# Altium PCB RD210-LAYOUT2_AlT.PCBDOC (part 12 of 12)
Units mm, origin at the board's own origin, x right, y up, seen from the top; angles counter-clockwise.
Board outline 250 x 123 mm, 4 copper layers (TOP, Mid-Layer 1, Mid-Layer 2, BOTTOM), stack 0.711 mm thick; 1043 components, 659 nets, 2786 pads, 1228 vias.
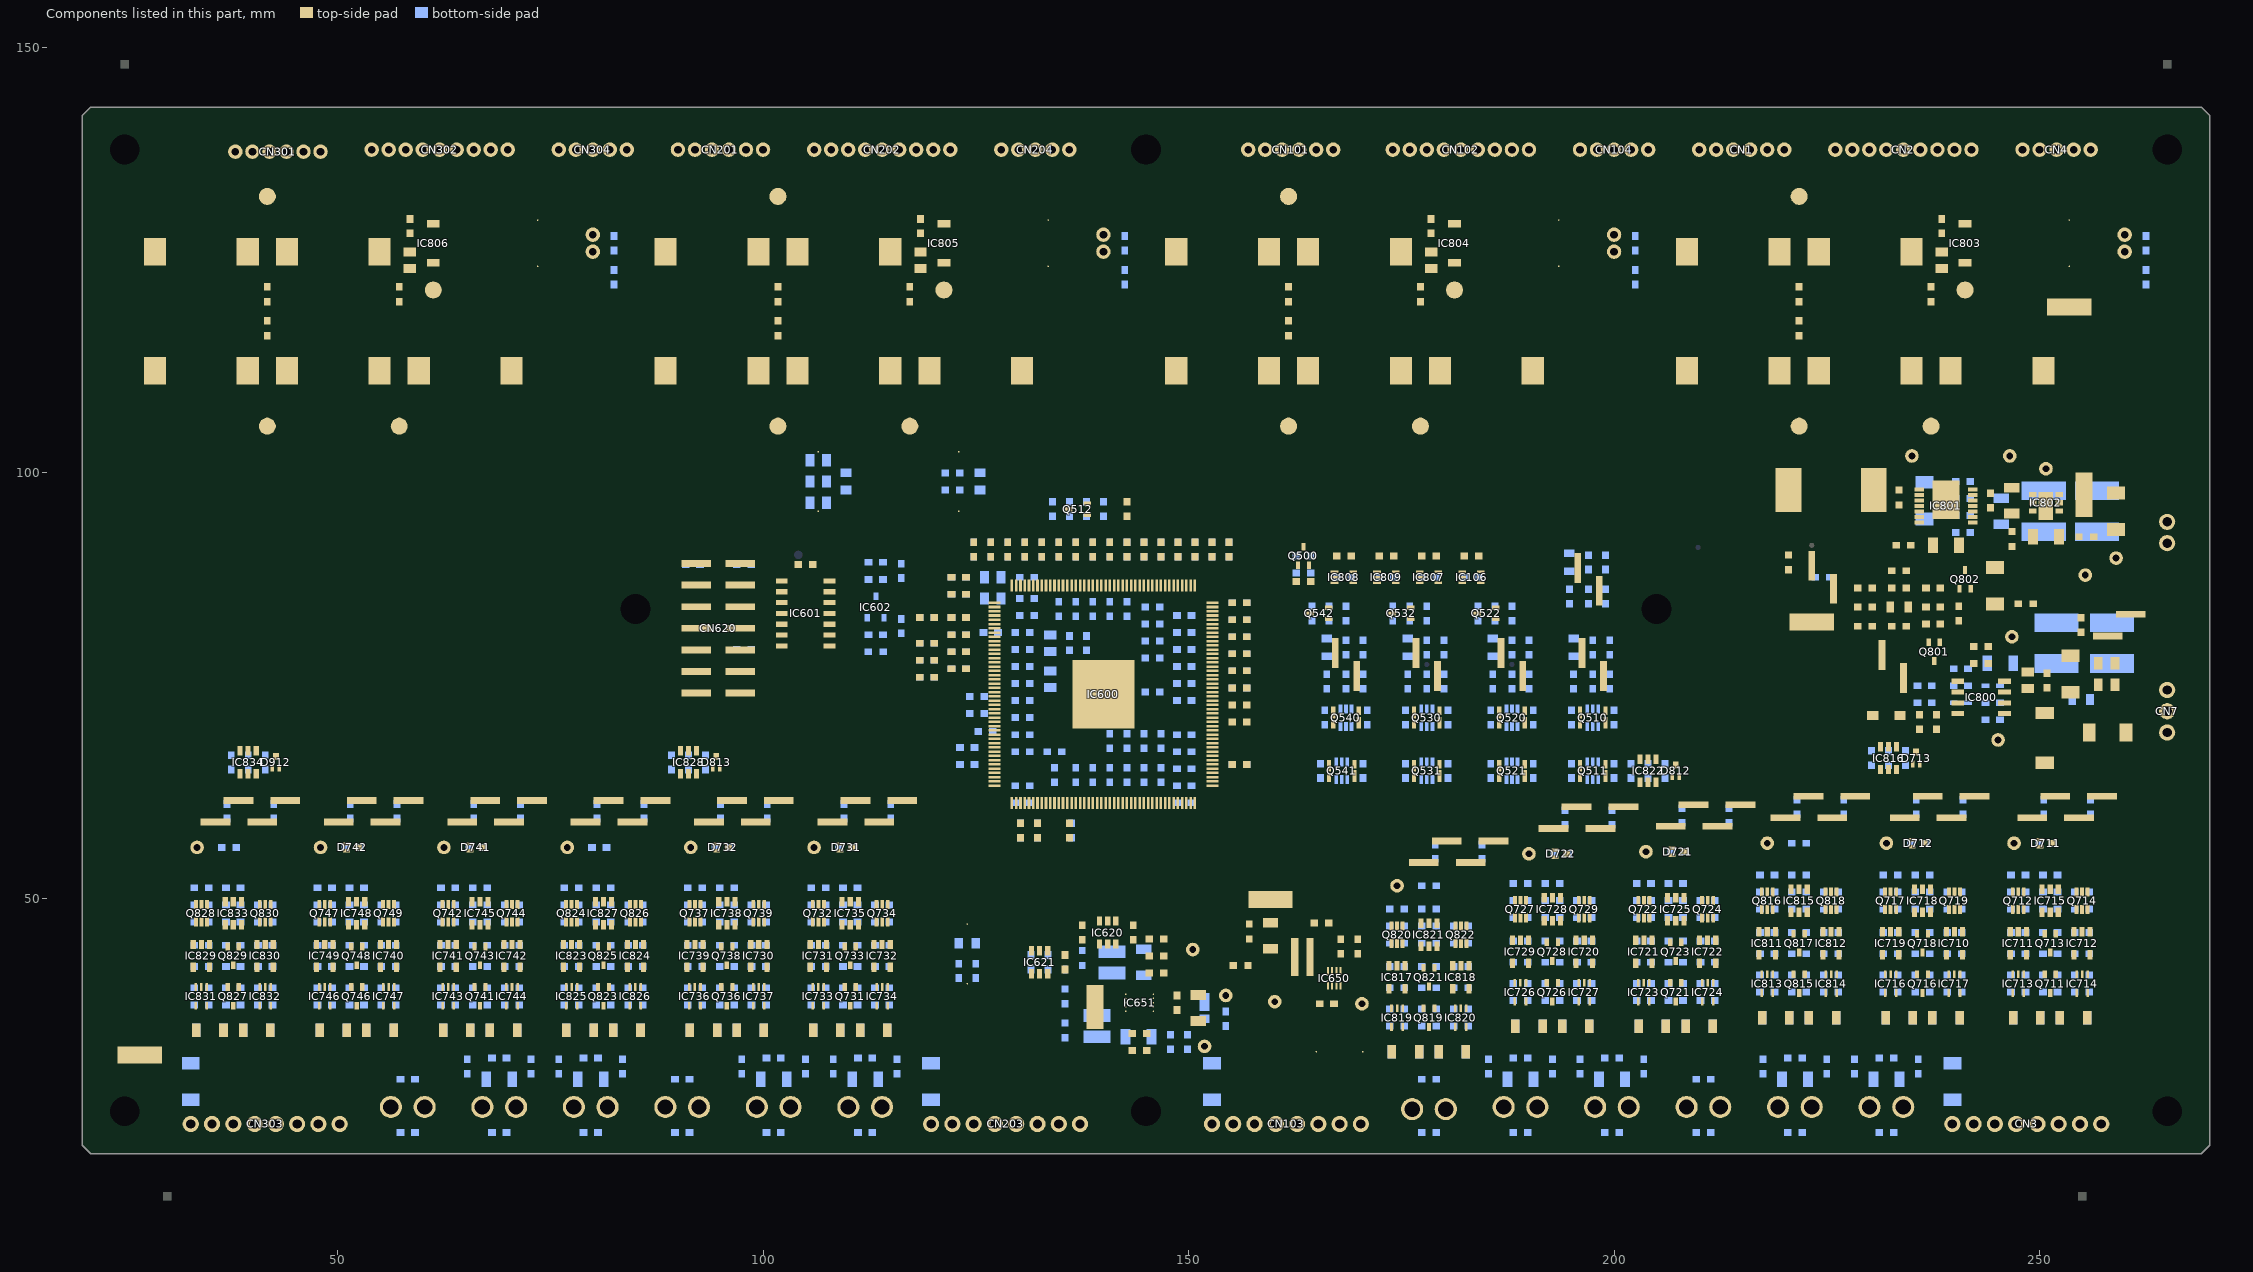
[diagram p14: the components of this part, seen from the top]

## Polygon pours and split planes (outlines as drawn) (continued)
no net on Top Overlay "TOPOVERLAY207" (solid, pour order 0): 203.75,135.825 ccw(c204,135.825) 204.25,135.825 ccw(c204,135.825)
no net on Top Overlay "TOPOVERLAY208" (solid, pour order 0): 197.55,125.9 ccw(c197.8,125.9) 198.05,125.9 ccw(c197.8,125.9)
no net on Top Overlay "TOPOVERLAY209" (solid, pour order 0): 99.75,135.825 ccw(c100,135.825) 100.25,135.825 ccw(c100,135.825)
no net on Top Overlay "TOPOVERLAY210" (solid, pour order 0): 121.75,135.825 ccw(c122,135.825) 122.25,135.825 ccw(c122,135.825)
no net on Top Overlay "TOPOVERLAY211" (solid, pour order 0): 135.75,135.825 ccw(c136,135.825) 136.25,135.825 ccw(c136,135.825)
no net on Top Overlay "TOPOVERLAY212" (solid, pour order 0): 137.55,125.9 ccw(c137.8,125.9) 138.05,125.9 ccw(c137.8,125.9)
no net on Top Overlay "TOPOVERLAY213" (solid, pour order 0): 47.75,135.575 ccw(c48,135.575) 48.25,135.575 ccw(c48,135.575)
no net on Top Overlay "TOPOVERLAY214" (solid, pour order 0): 69.75,135.825 ccw(c70,135.825) 70.25,135.825 ccw(c70,135.825)
no net on Top Overlay "TOPOVERLAY215" (solid, pour order 0): 83.75,135.825 ccw(c84,135.825) 84.25,135.825 ccw(c84,135.825)
no net on Top Overlay "TOPOVERLAY216" (solid, pour order 0): 77.55,125.9 ccw(c77.8,125.9) 78.05,125.9 ccw(c77.8,125.9)
no net on Top Overlay "TOPOVERLAY217" (solid, pour order 0): 138.8,95.1 ccw(c139.05,95.1) 139.3,95.1 ccw(c139.05,95.1)
no net on Top Overlay "TOPOVERLAY218" (solid, pour order 0): 251.925,77.325 251.925,78.275 252.425,78.275 252.425,77.625 254.825,77.625 254.825,78.275 255.325,78.275 255.325,77.325
no net on Top Overlay "TOPOVERLAY219" (solid, pour order 0): 243.05,87.7 243.05,88.65 243.55,88.65 243.55,88 245.95,88 245.95,88.65 246.45,88.65 246.45,87.7
no net on Top Overlay "TOPOVERLAY220" (solid, pour order 0): 232.5,70.2 232.5,72.8 233.3,72.8 233.3,72.2 232.8,72.2 232.8,70.8 233.3,70.8 233.3,70.2
no net on Top Overlay "TOPOVERLAY221" (solid, pour order 0): 256.1,67.8 256.1,68.3 256.75,68.3 256.75,70.7 256.1,70.7 256.1,71.2 257.05,71.2 257.05,67.8
no net on Top Overlay "TOPOVERLAY222" (solid, pour order 0): 175.95,88.4 ccw(c176.2,88.4) 176.45,88.4 ccw(c176.2,88.4)
no net on Top Overlay "TOPOVERLAY223" (solid, pour order 0): 165.95,88.4 ccw(c166.2,88.4) 166.45,88.4 ccw(c166.2,88.4)
no net on Top Overlay "TOPOVERLAY224" (solid, pour order 0): 170.95,88.4 ccw(c171.2,88.4) 171.45,88.4 ccw(c171.2,88.4)
no net on Top Overlay "TOPOVERLAY225" (solid, pour order 0): 234.625,98.625 ccw(c234.875,98.625) 235.125,98.625 ccw(c234.875,98.625)
no net on Top Overlay "TOPOVERLAY226" (solid, pour order 0): 246.875,71.72 ccw(c247.125,71.72) 247.375,71.72 ccw(c247.125,71.72)
no net on Top Overlay "TOPOVERLAY227" (solid, pour order 0): 257.3,93.6 257.3,94.55 260.7,94.55 260.7,93.6 260.2,93.6 260.2,94.25 257.8,94.25 257.8,93.6
no net on Top Overlay "TOPOVERLAY228" (solid, pour order 0): 196.425,70.35 196.425,70.85 196.925,70.85 196.925,70.35
no net on Top Overlay "TOPOVERLAY229" (solid, pour order 0): 195.075,70.35 195.075,70.85 195.575,70.85 195.575,70.35
no net on Top Overlay "TOPOVERLAY230" (solid, pour order 0): 198.075,65.4 198.075,65.9 198.575,65.9 198.575,65.4
no net on Top Overlay "TOPOVERLAY231" (solid, pour order 0): 199.425,65.4 199.425,65.9 199.925,65.9 199.925,65.4
no net on Top Overlay "TOPOVERLAY232" (solid, pour order 0): 196.425,64.1 196.425,64.6 196.925,64.6 196.925,64.1
no net on Top Overlay "TOPOVERLAY233" (solid, pour order 0): 195.075,64.1 195.075,64.6 195.575,64.6 195.575,64.1
no net on Top Overlay "TOPOVERLAY234" (solid, pour order 0): 188.575,65.4 188.575,65.9 189.075,65.9 189.075,65.4
no net on Top Overlay "TOPOVERLAY235" (solid, pour order 0): 189.925,65.4 189.925,65.9 190.425,65.9 190.425,65.4
no net on Top Overlay "TOPOVERLAY236" (solid, pour order 0): 186.925,64.1 186.925,64.6 187.425,64.6 187.425,64.1
no net on Top Overlay "TOPOVERLAY237" (solid, pour order 0): 185.575,64.1 185.575,64.6 186.075,64.6 186.075,64.1
no net on Top Overlay "TOPOVERLAY238" (solid, pour order 0): 168.575,65.4 168.575,65.9 169.075,65.9 169.075,65.4
no net on Top Overlay "TOPOVERLAY239" (solid, pour order 0): 169.925,65.4 169.925,65.9 170.425,65.9 170.425,65.4
no net on Top Overlay "TOPOVERLAY240" (solid, pour order 0): 166.925,64.1 166.925,64.6 167.425,64.6 167.425,64.1
no net on Top Overlay "TOPOVERLAY241" (solid, pour order 0): 165.575,64.1 165.575,64.6 166.075,64.6 166.075,64.1
no net on Top Overlay "TOPOVERLAY242" (solid, pour order 0): 167.425,70.35 167.425,70.85 167.925,70.85 167.925,70.35
no net on Top Overlay "TOPOVERLAY243" (solid, pour order 0): 166.075,70.35 166.075,70.85 166.575,70.85 166.575,70.35
no net on Top Overlay "TOPOVERLAY244" (solid, pour order 0): 186.925,70.35 186.925,70.85 187.425,70.85 187.425,70.35
no net on Top Overlay "TOPOVERLAY245" (solid, pour order 0): 185.575,70.35 185.575,70.85 186.075,70.85 186.075,70.35
no net on Top Overlay "TOPOVERLAY246" (solid, pour order 0): 176.925,64.1 176.925,64.6 177.425,64.6 177.425,64.1
no net on Top Overlay "TOPOVERLAY247" (solid, pour order 0): 175.575,64.1 175.575,64.6 176.075,64.6 176.075,64.1
no net on Top Overlay "TOPOVERLAY248" (solid, pour order 0): 178.575,65.4 178.575,65.9 179.075,65.9 179.075,65.4
no net on Top Overlay "TOPOVERLAY249" (solid, pour order 0): 179.925,65.4 179.925,65.9 180.425,65.9 180.425,65.4
no net on Top Overlay "TOPOVERLAY250" (solid, pour order 0): 176.925,70.35 176.925,70.85 177.425,70.85 177.425,70.35
no net on Top Overlay "TOPOVERLAY251" (solid, pour order 0): 175.575,70.35 175.575,70.85 176.075,70.85 176.075,70.35
no net on Top Overlay "TOPOVERLAY252" (solid, pour order 0): 190.73,30.775 ccw(c190.98,30.775) 191.23,30.775 ccw(c190.98,30.775)
no net on Top Overlay "TOPOVERLAY253" (solid, pour order 0): 113.73,30.775 ccw(c113.98,30.775) 114.23,30.775 ccw(c113.98,30.775)
no net on Top Overlay "TOPOVERLAY254" (solid, pour order 0): 102.98,30.775 ccw(c103.23,30.775) 103.48,30.775 ccw(c103.23,30.775)
no net on Top Overlay "TOPOVERLAY255" (solid, pour order 0): 81.48,30.775 ccw(c81.73,30.775) 81.98,30.775 ccw(c81.73,30.775)
no net on Top Overlay "TOPOVERLAY256" (solid, pour order 0): 70.73,30.775 ccw(c70.98,30.775) 71.23,30.775 ccw(c70.98,30.775)
no net on Top Overlay "TOPOVERLAY257" (solid, pour order 0): 233.73,30.775 ccw(c233.98,30.775) 234.23,30.775 ccw(c233.98,30.775)
no net on Top Overlay "TOPOVERLAY258" (solid, pour order 0): 222.98,30.775 ccw(c223.23,30.775) 223.48,30.775 ccw(c223.23,30.775)
no net on Top Overlay "TOPOVERLAY259" (solid, pour order 0): 201.48,30.775 ccw(c201.73,30.775) 201.98,30.775 ccw(c201.73,30.775)
no net on Top Overlay "TOPOVERLAY260" (solid, pour order 0): 212.23,30.775 ccw(c212.48,30.775) 212.73,30.775 ccw(c212.48,30.775)
no net on Top Overlay "TOPOVERLAY261" (solid, pour order 0): 179.98,30.525 ccw(c180.23,30.525) 180.48,30.525 ccw(c180.23,30.525)
no net on Top Overlay "TOPOVERLAY262" (solid, pour order 0): 92.23,30.775 ccw(c92.48,30.775) 92.73,30.775 ccw(c92.48,30.775)
no net on Top Overlay "TOPOVERLAY263" (solid, pour order 0): 59.98,30.775 ccw(c60.23,30.775) 60.48,30.775 ccw(c60.23,30.775)
no net on Top Overlay "TOPOVERLAY264" (solid, pour order 0): 240.7,47.15 ccw(c240.95,47.15) 241.2,47.15 ccw(c240.95,47.15)
no net on Top Overlay "TOPOVERLAY265" (solid, pour order 0): 248.2,47.15 ccw(c248.45,47.15) 248.7,47.15 ccw(c248.45,47.15)
no net on Top Overlay "TOPOVERLAY266" (solid, pour order 0): 255.7,47.15 ccw(c255.95,47.15) 256.2,47.15 ccw(c255.95,47.15)
no net on Top Overlay "TOPOVERLAY267" (solid, pour order 0): 252.575,51.625 ccw(c252.875,51.625) 253.175,51.625 ccw(c252.875,51.625)
no net on Top Overlay "TOPOVERLAY268" (solid, pour order 0): 233.375,41.75 ccw(c233.625,41.75) 233.875,41.75 ccw(c233.625,41.75)
no net on Top Overlay "TOPOVERLAY269" (solid, pour order 0): 241,41.625 ccw(c241.25,41.625) 241.5,41.625 ccw(c241.25,41.625)
no net on Top Overlay "TOPOVERLAY270" (solid, pour order 0): 237.7,51.875 ccw(c238,51.875) 238.3,51.875 ccw(c238,51.875)
no net on Top Overlay "TOPOVERLAY271" (solid, pour order 0): 233.2,47.15 ccw(c233.45,47.15) 233.7,47.15 ccw(c233.45,47.15)
no net on Top Overlay "TOPOVERLAY272" (solid, pour order 0): 197.2,46.15 ccw(c197.45,46.15) 197.7,46.15 ccw(c197.45,46.15)
no net on Top Overlay "TOPOVERLAY273" (solid, pour order 0): 204.2,46.15 ccw(c204.45,46.15) 204.7,46.15 ccw(c204.45,46.15)
no net on Top Overlay "TOPOVERLAY274" (solid, pour order 0): 211.7,46.15 ccw(c211.95,46.15) 212.2,46.15 ccw(c211.95,46.15)
no net on Top Overlay "TOPOVERLAY275" (solid, pour order 0): 204.375,40.75 ccw(c204.625,40.75) 204.875,40.75 ccw(c204.625,40.75)
no net on Top Overlay "TOPOVERLAY276" (solid, pour order 0): 211.4,41.05 ccw(c211.65,41.05) 211.9,41.05 ccw(c211.65,41.05)
no net on Top Overlay "TOPOVERLAY277" (solid, pour order 0): 208.7,50.625 ccw(c209,50.625) 209.3,50.625 ccw(c209,50.625)
no net on Top Overlay "TOPOVERLAY278" (solid, pour order 0): 189.875,40.875 ccw(c190.125,40.875) 190.375,40.875 ccw(c190.125,40.875)
no net on Top Overlay "TOPOVERLAY279" (solid, pour order 0): 196.9,41.05 ccw(c197.15,41.05) 197.4,41.05 ccw(c197.15,41.05)
no net on Top Overlay "TOPOVERLAY280" (solid, pour order 0): 193.575,51.25 ccw(c193.875,51.25) 194.175,51.25 ccw(c193.875,51.25)
no net on Top Overlay "TOPOVERLAY281" (solid, pour order 0): 189.7,46.15 ccw(c189.95,46.15) 190.2,46.15 ccw(c189.95,46.15)
no net on Top Overlay "TOPOVERLAY282" (solid, pour order 0): 100.2,45.65 ccw(c100.45,45.65) 100.7,45.65 ccw(c100.45,45.65)
no net on Top Overlay "TOPOVERLAY283" (solid, pour order 0): 107.2,45.65 ccw(c107.45,45.65) 107.7,45.65 ccw(c107.45,45.65)
no net on Top Overlay "TOPOVERLAY284" (solid, pour order 0): 114.7,45.65 ccw(c114.95,45.65) 115.2,45.65 ccw(c114.95,45.65)
no net on Top Overlay "TOPOVERLAY285" (solid, pour order 0): 107.375,40.375 ccw(c107.625,40.375) 107.875,40.375 ccw(c107.625,40.375)
no net on Top Overlay "TOPOVERLAY286" (solid, pour order 0): 114.4,40.55 ccw(c114.65,40.55) 114.9,40.55 ccw(c114.65,40.55)
no net on Top Overlay "TOPOVERLAY287" (solid, pour order 0): 110.9,50.65 ccw(c111.2,50.65) 111.5,50.65 ccw(c111.2,50.65)
no net on Top Overlay "TOPOVERLAY288" (solid, pour order 0): 92.875,40.25 ccw(c93.125,40.25) 93.375,40.25 ccw(c93.125,40.25)
no net on Top Overlay "TOPOVERLAY289" (solid, pour order 0): 99.9,40.55 ccw(c100.15,40.55) 100.4,40.55 ccw(c100.15,40.55)
no net on Top Overlay "TOPOVERLAY290" (solid, pour order 0): 96.4,50.65 ccw(c96.7,50.65) 97,50.65 ccw(c96.7,50.65)
no net on Top Overlay "TOPOVERLAY291" (solid, pour order 0): 92.7,45.65 ccw(c92.95,45.65) 93.2,45.65 ccw(c92.95,45.65)
no net on Top Overlay "TOPOVERLAY292" (solid, pour order 0): 56.7,45.65 ccw(c56.95,45.65) 57.2,45.65 ccw(c56.95,45.65)
no net on Top Overlay "TOPOVERLAY293" (solid, pour order 0): 63.7,45.65 ccw(c63.95,45.65) 64.2,45.65 ccw(c63.95,45.65)
no net on Top Overlay "TOPOVERLAY294" (solid, pour order 0): 71.2,45.65 ccw(c71.45,45.65) 71.7,45.65 ccw(c71.45,45.65)
no net on Top Overlay "TOPOVERLAY295" (solid, pour order 0): 64,40.375 ccw(c64.25,40.375) 64.5,40.375 ccw(c64.25,40.375)
no net on Top Overlay "TOPOVERLAY296" (solid, pour order 0): 70.9,40.55 ccw(c71.15,40.55) 71.4,40.55 ccw(c71.15,40.55)
no net on Top Overlay "TOPOVERLAY297" (solid, pour order 0): 67.4,50.65 ccw(c67.7,50.65) 68,50.65 ccw(c67.7,50.65)
no net on Top Overlay "TOPOVERLAY298" (solid, pour order 0): 49.375,40.25 ccw(c49.625,40.25) 49.875,40.25 ccw(c49.625,40.25)
no net on Top Overlay "TOPOVERLAY299" (solid, pour order 0): 56.4,40.55 ccw(c56.65,40.55) 56.9,40.55 ccw(c56.65,40.55)
no net on Top Overlay "TOPOVERLAY300" (solid, pour order 0): 52.9,50.65 ccw(c53.2,50.65) 53.5,50.65 ccw(c53.2,50.65)
no net on Top Overlay "TOPOVERLAY301" (solid, pour order 0): 49.2,45.65 ccw(c49.45,45.65) 49.7,45.65 ccw(c49.45,45.65)
no net on Top Overlay "TOPOVERLAY302" (solid, pour order 0): 218.7,47.15 ccw(c218.95,47.15) 219.2,47.15 ccw(c218.95,47.15)
no net on Top Overlay "TOPOVERLAY303" (solid, pour order 0): 226.2,47.15 ccw(c226.45,47.15) 226.7,47.15 ccw(c226.45,47.15)
no net on Top Overlay "TOPOVERLAY304" (solid, pour order 0): 218.875,41.75 ccw(c219.125,41.75) 219.375,41.75 ccw(c219.125,41.75)
no net on Top Overlay "TOPOVERLAY305" (solid, pour order 0): 225.9,42.05 ccw(c226.15,42.05) 226.4,42.05 ccw(c226.15,42.05)
no net on Top Overlay "TOPOVERLAY306" (solid, pour order 0): 223.2,51.75 ccw(c223.5,51.75) 223.8,51.75 ccw(c223.5,51.75)
no net on Top Overlay "TOPOVERLAY307" (solid, pour order 0): 231,64.1 ccw(c231.3,64.1) 231.6,64.1 ccw(c231.3,64.1)
no net on Top Overlay "TOPOVERLAY308" (solid, pour order 0): 175.2,43.15 ccw(c175.45,43.15) 175.7,43.15 ccw(c175.45,43.15)
no net on Top Overlay "TOPOVERLAY309" (solid, pour order 0): 182.7,43.15 ccw(c182.95,43.15) 183.2,43.15 ccw(c182.95,43.15)
no net on Top Overlay "TOPOVERLAY310" (solid, pour order 0): 175.375,37.75 ccw(c175.625,37.75) 175.875,37.75 ccw(c175.625,37.75)
no net on Top Overlay "TOPOVERLAY311" (solid, pour order 0): 182.4,38.05 ccw(c182.65,38.05) 182.9,38.05 ccw(c182.65,38.05)
no net on Top Overlay "TOPOVERLAY312" (solid, pour order 0): 179.7,47.625 ccw(c180,47.625) 180.3,47.625 ccw(c180,47.625)
no net on Top Overlay "TOPOVERLAY313" (solid, pour order 0): 78.2,45.65 ccw(c78.45,45.65) 78.7,45.65 ccw(c78.45,45.65)
no net on Top Overlay "TOPOVERLAY314" (solid, pour order 0): 85.7,45.65 ccw(c85.95,45.65) 86.2,45.65 ccw(c85.95,45.65)
no net on Top Overlay "TOPOVERLAY315" (solid, pour order 0): 78.375,40.25 ccw(c78.625,40.25) 78.875,40.25 ccw(c78.625,40.25)
no net on Top Overlay "TOPOVERLAY316" (solid, pour order 0): 85.4,40.55 ccw(c85.65,40.55) 85.9,40.55 ccw(c85.65,40.55)
no net on Top Overlay "TOPOVERLAY317" (solid, pour order 0): 81.9,50.65 ccw(c82.2,50.65) 82.5,50.65 ccw(c82.2,50.65)
no net on Top Overlay "TOPOVERLAY318" (solid, pour order 0): 90,63.6 ccw(c90.3,63.6) 90.6,63.6 ccw(c90.3,63.6)
no net on Top Overlay "TOPOVERLAY319" (solid, pour order 0): 34.7,45.65 ccw(c34.95,45.65) 35.2,45.65 ccw(c34.95,45.65)
no net on Top Overlay "TOPOVERLAY320" (solid, pour order 0): 42.2,45.65 ccw(c42.45,45.65) 42.7,45.65 ccw(c42.45,45.65)
no net on Top Overlay "TOPOVERLAY321" (solid, pour order 0): 34.875,40.25 ccw(c35.125,40.25) 35.375,40.25 ccw(c35.125,40.25)
no net on Top Overlay "TOPOVERLAY322" (solid, pour order 0): 41.9,40.55 ccw(c42.15,40.55) 42.4,40.55 ccw(c42.15,40.55)
no net on Top Overlay "TOPOVERLAY323" (solid, pour order 0): 38.4,50.65 ccw(c38.7,50.65) 39,50.65 ccw(c38.7,50.65)
no net on Top Overlay "TOPOVERLAY324" (solid, pour order 0): 38.25,63.6 ccw(c38.55,63.6) 38.85,63.6 ccw(c38.55,63.6)
no net on Top Overlay "TOPOVERLAY325" (solid, pour order 0): 250.35,37.95 ccw(c250.6,37.95) 250.85,37.95 ccw(c250.6,37.95)
no net on Top Overlay "TOPOVERLAY326" (solid, pour order 0): 249.875,42.875 ccw(c250.125,42.875) 250.375,42.875 ccw(c250.125,42.875)
no net on Top Overlay "TOPOVERLAY327" (solid, pour order 0): 254.1,47.7 ccw(c254.35,47.7) 254.6,47.7 ccw(c254.35,47.7)
no net on Top Overlay "TOPOVERLAY328" (solid, pour order 0): 235.875,38.125 ccw(c236.125,38.125) 236.375,38.125 ccw(c236.125,38.125)
no net on Top Overlay "TOPOVERLAY329" (solid, pour order 0): 231.6,47.7 ccw(c231.85,47.7) 232.1,47.7 ccw(c231.85,47.7)
no net on Top Overlay "TOPOVERLAY330" (solid, pour order 0): 234.875,42.875 ccw(c235.125,42.875) 235.375,42.875 ccw(c235.125,42.875)
no net on Top Overlay "TOPOVERLAY331" (solid, pour order 0): 239.1,47.7 ccw(c239.35,47.7) 239.6,47.7 ccw(c239.35,47.7)
no net on Top Overlay "TOPOVERLAY332" (solid, pour order 0): 205.875,36.5 ccw(c206.125,36.5) 206.375,36.5 ccw(c206.125,36.5)
no net on Top Overlay "TOPOVERLAY333" (solid, pour order 0): 202.6,46.7 ccw(c202.85,46.7) 203.1,46.7 ccw(c202.85,46.7)
no net on Top Overlay "TOPOVERLAY334" (solid, pour order 0): 205.875,41.875 ccw(c206.125,41.875) 206.375,41.875 ccw(c206.125,41.875)
no net on Top Overlay "TOPOVERLAY335" (solid, pour order 0): 210.1,46.7 ccw(c210.35,46.7) 210.6,46.7 ccw(c210.35,46.7)
no net on Top Overlay "TOPOVERLAY336" (solid, pour order 0): 191.375,36.5 ccw(c191.625,36.5) 191.875,36.5 ccw(c191.625,36.5)
no net on Top Overlay "TOPOVERLAY337" (solid, pour order 0): 188.1,46.7 ccw(c188.35,46.7) 188.6,46.7 ccw(c188.35,46.7)
no net on Top Overlay "TOPOVERLAY338" (solid, pour order 0): 191.375,41.875 ccw(c191.625,41.875) 191.875,41.875 ccw(c191.625,41.875)
no net on Top Overlay "TOPOVERLAY339" (solid, pour order 0): 195.6,46.7 ccw(c195.85,46.7) 196.1,46.7 ccw(c195.85,46.7)
no net on Top Overlay "TOPOVERLAY340" (solid, pour order 0): 108.875,36.25 ccw(c109.125,36.25) 109.375,36.25 ccw(c109.125,36.25)
no net on Top Overlay "TOPOVERLAY341" (solid, pour order 0): 105.6,46.2 ccw(c105.85,46.2) 106.1,46.2 ccw(c105.85,46.2)
no net on Top Overlay "TOPOVERLAY342" (solid, pour order 0): 109,41.375 ccw(c109.25,41.375) 109.5,41.375 ccw(c109.25,41.375)
no net on Top Overlay "TOPOVERLAY343" (solid, pour order 0): 113.1,46.2 ccw(c113.35,46.2) 113.6,46.2 ccw(c113.35,46.2)
no net on Top Overlay "TOPOVERLAY344" (solid, pour order 0): 94.375,36 ccw(c94.625,36) 94.875,36 ccw(c94.625,36)
no net on Top Overlay "TOPOVERLAY345" (solid, pour order 0): 91.1,46.2 ccw(c91.35,46.2) 91.6,46.2 ccw(c91.35,46.2)
no net on Top Overlay "TOPOVERLAY346" (solid, pour order 0): 94.25,41.25 ccw(c94.5,41.25) 94.75,41.25 ccw(c94.5,41.25)
no net on Top Overlay "TOPOVERLAY347" (solid, pour order 0): 98.6,46.2 ccw(c98.85,46.2) 99.1,46.2 ccw(c98.85,46.2)
no net on Top Overlay "TOPOVERLAY348" (solid, pour order 0): 65.375,36 ccw(c65.625,36) 65.875,36 ccw(c65.625,36)
no net on Top Overlay "TOPOVERLAY349" (solid, pour order 0): 62.1,46.2 ccw(c62.35,46.2) 62.6,46.2 ccw(c62.35,46.2)
no net on Top Overlay "TOPOVERLAY350" (solid, pour order 0): 65.25,41.25 ccw(c65.5,41.25) 65.75,41.25 ccw(c65.5,41.25)
no net on Top Overlay "TOPOVERLAY351" (solid, pour order 0): 69.6,46.2 ccw(c69.85,46.2) 70.1,46.2 ccw(c69.85,46.2)
no net on Top Overlay "TOPOVERLAY352" (solid, pour order 0): 50.875,36 ccw(c51.125,36) 51.375,36 ccw(c51.125,36)
no net on Top Overlay "TOPOVERLAY353" (solid, pour order 0): 47.6,46.2 ccw(c47.85,46.2) 48.1,46.2 ccw(c47.85,46.2)
no net on Top Overlay "TOPOVERLAY354" (solid, pour order 0): 50.75,41.25 ccw(c51,41.25) 51.25,41.25 ccw(c51,41.25)
no net on Top Overlay "TOPOVERLAY355" (solid, pour order 0): 55.1,46.2 ccw(c55.35,46.2) 55.6,46.2 ccw(c55.35,46.2)
no net on Top Overlay "TOPOVERLAY356" (solid, pour order 0): 220.25,37.75 ccw(c220.5,37.75) 220.75,37.75 ccw(c220.5,37.75)
no net on Top Overlay "TOPOVERLAY357" (solid, pour order 0): 217.1,47.7 ccw(c217.35,47.7) 217.6,47.7 ccw(c217.35,47.7)
no net on Top Overlay "TOPOVERLAY358" (solid, pour order 0): 220.375,42.875 ccw(c220.625,42.875) 220.875,42.875 ccw(c220.625,42.875)
no net on Top Overlay "TOPOVERLAY359" (solid, pour order 0): 224.6,47.7 ccw(c224.85,47.7) 225.1,47.7 ccw(c224.85,47.7)
no net on Top Overlay "TOPOVERLAY360" (solid, pour order 0): 176.75,33.75 ccw(c177,33.75) 177.25,33.75 ccw(c177,33.75)
no net on Top Overlay "TOPOVERLAY361" (solid, pour order 0): 176.875,38.875 ccw(c177.125,38.875) 177.375,38.875 ccw(c177.125,38.875)
no net on Top Overlay "TOPOVERLAY362" (solid, pour order 0): 181.1,43.7 ccw(c181.35,43.7) 181.6,43.7 ccw(c181.35,43.7)
no net on Top Overlay "TOPOVERLAY363" (solid, pour order 0): 79.875,36 ccw(c80.125,36) 80.375,36 ccw(c80.125,36)
no net on Top Overlay "TOPOVERLAY364" (solid, pour order 0): 76.6,46.2 ccw(c76.85,46.2) 77.1,46.2 ccw(c76.85,46.2)
no net on Top Overlay "TOPOVERLAY365" (solid, pour order 0): 79.75,41.25 ccw(c80,41.25) 80.25,41.25 ccw(c80,41.25)
no net on Top Overlay "TOPOVERLAY366" (solid, pour order 0): 84.1,46.2 ccw(c84.35,46.2) 84.6,46.2 ccw(c84.35,46.2)
no net on Top Overlay "TOPOVERLAY367" (solid, pour order 0): 36.375,36 ccw(c36.625,36) 36.875,36 ccw(c36.625,36)
no net on Top Overlay "TOPOVERLAY368" (solid, pour order 0): 33.125,46.25 ccw(c33.375,46.25) 33.625,46.25 ccw(c33.375,46.25)
no net on Top Overlay "TOPOVERLAY369" (solid, pour order 0): 36.25,41.25 ccw(c36.5,41.25) 36.75,41.25 ccw(c36.5,41.25)
no net on Top Overlay "TOPOVERLAY370" (solid, pour order 0): 40.6,46.2 ccw(c40.85,46.2) 41.1,46.2 ccw(c40.85,46.2)
no net on Top Overlay "TOPOVERLAY371" (solid, pour order 0): 261.9,69.5 ccw(c262.15,69.5) 262.4,69.5 ccw(c262.15,69.5)
no net on Top Overlay "TOPOVERLAY372" (solid, pour order 0): 198.075,71.65 198.075,72.15 198.575,72.15 198.575,71.65
no net on Top Overlay "TOPOVERLAY373" (solid, pour order 0): 199.425,71.65 199.425,72.15 199.925,72.15 199.925,71.65
no net on Top Overlay "TOPOVERLAY374" (solid, pour order 0): 247.948,71.36 cw(c248.019,71.431) 248.09,71.502
no net on Top Overlay "TOPOVERLAY375" (solid, pour order 0): 253.231,66.219 cw(c253.231,66.319) 253.16,66.248 253.302,66.39 cw(c253.231,66.319) 253.231,66.219
no net on Top Overlay "TOPOVERLAY376" (solid, pour order 0): 169.075,71.65 169.075,72.15 169.575,72.15 169.575,71.65
no net on Top Overlay "TOPOVERLAY377" (solid, pour order 0): 170.425,71.65 170.425,72.15 170.925,72.15 170.925,71.65
no net on Top Overlay "TOPOVERLAY378" (solid, pour order 0): 188.575,71.65 188.575,72.15 189.075,72.15 189.075,71.65
no net on Top Overlay "TOPOVERLAY379" (solid, pour order 0): 189.925,71.65 189.925,72.15 190.425,72.15 190.425,71.65
no net on Top Overlay "TOPOVERLAY380" (solid, pour order 0): 178.575,71.65 178.575,72.15 179.075,72.15 179.075,71.65
no net on Top Overlay "TOPOVERLAY381" (solid, pour order 0): 179.925,71.65 179.925,72.15 180.425,72.15 180.425,71.65
no net on Top Overlay "TOPOVERLAY382" (solid, pour order 0): 165.75,29.566 cw(c167.75,32) 164.673,31.325 165.75,31.325
no net on Top Overlay "TOPOVERLAY383" (solid, pour order 0): 164.673,32.675 cw(c167.75,32) 165.75,34.434 165.75,32.675
no net on Top Overlay "TOPOVERLAY384" (solid, pour order 0): 248.375,41.75 ccw(c248.625,41.75) 248.875,41.75 ccw(c248.625,41.75)
no net on Top Overlay "TOPOVERLAY385" (solid, pour order 0): 246.625,47.75 ccw(c246.875,47.75) 247.125,47.75 ccw(c246.875,47.75)
no net on Top Overlay "TOPOVERLAY386" (solid, pour order 0): 255.4,42.05 ccw(c255.65,42.05) 255.9,42.05 ccw(c255.65,42.05)
no net on Top Overlay "TOPOVERLAY387" (solid, pour order 0): 173.625,43.75 ccw(c173.875,43.75) 174.125,43.75 ccw(c173.875,43.75)
no net on Top Overlay "TOPOVERLAY388" (solid, pour order 0): 202.75,62.6 ccw(c203.05,62.6) 203.35,62.6 ccw(c203.05,62.6)
no net on Bottom Overlay "BOTTOMOVERLAY389" (solid, pour order 0): 31.05,29.45 31.05,30.4 31.55,30.4 31.55,29.75 33.95,29.75 33.95,30.4 34.45,30.4 34.45,29.45
no net on Bottom Overlay "BOTTOMOVERLAY390" (solid, pour order 0): 150.675,37.625 150.675,38.125 151.125,38.125 151.125,37.625
no net on Bottom Overlay "BOTTOMOVERLAY391" (solid, pour order 0): 152.625,37.625 152.625,38.125 153.075,38.125 153.075,37.625
no net on Bottom Overlay "BOTTOMOVERLAY392" (solid, pour order 0): 198.5,69.375 ccw(c198.75,69.375) 199,69.375 ccw(c198.75,69.375)
no net on Bottom Overlay "BOTTOMOVERLAY393" (solid, pour order 0): 197.9,62.95 ccw(c198.15,62.95) 198.4,62.95 ccw(c198.15,62.95)
no net on Bottom Overlay "BOTTOMOVERLAY394" (solid, pour order 0): 188.4,62.95 ccw(c188.65,62.95) 188.9,62.95 ccw(c188.65,62.95)
no net on Bottom Overlay "BOTTOMOVERLAY395" (solid, pour order 0): 169.375,69.375 ccw(c169.625,69.375) 169.875,69.375 ccw(c169.625,69.375)
no net on Bottom Overlay "BOTTOMOVERLAY396" (solid, pour order 0): 168.4,63 ccw(c168.65,63) 168.9,63 ccw(c168.65,63)
no net on Bottom Overlay "BOTTOMOVERLAY397" (solid, pour order 0): 188.875,69.375 ccw(c189.125,69.375) 189.375,69.375 ccw(c189.125,69.375)
no net on Bottom Overlay "BOTTOMOVERLAY398" (solid, pour order 0): 178.4,63 ccw(c178.65,63) 178.9,63 ccw(c178.65,63)
no net on Bottom Overlay "BOTTOMOVERLAY399" (solid, pour order 0): 178.85,69.375 ccw(c179.1,69.375) 179.35,69.375 ccw(c179.1,69.375)
no net on Bottom Overlay "BOTTOMOVERLAY400" (solid, pour order 0): 134.6,41.9 134.6,42.4 136.4,42.4 136.4,41.9 135.9,41.9 135.9,42.25 135.1,42.25 135.1,41.9
no net on Bottom Overlay "BOTTOMOVERLAY401" (solid, pour order 0): 118.05,29.45 118.05,30.4 118.55,30.4 118.55,29.75 120.95,29.75 120.95,30.4 121.45,30.4 121.45,29.45
no net on Bottom Overlay "BOTTOMOVERLAY402" (solid, pour order 0): 151.05,29.45 151.05,30.4 151.55,30.4 151.55,29.75 153.95,29.75 153.95,30.4 154.45,30.4 154.45,29.45
no net on Bottom Overlay "BOTTOMOVERLAY403" (solid, pour order 0): 238.05,29.45 238.05,30.4 238.55,30.4 238.55,29.75 240.95,29.75 240.95,30.4 241.45,30.4 241.45,29.45
no net on Bottom Overlay "BOTTOMOVERLAY404" (solid, pour order 0): 244.6,74.1 244.6,75.9 245.1,75.9 245.1,75.4 244.75,75.4 244.75,74.6 245.1,74.6 245.1,74.1
no net on Bottom Overlay "BOTTOMOVERLAY405" (solid, pour order 0): 234.8,97.7 234.8,98.65 235.3,98.65 235.3,98 237.7,98 237.7,98.65 238.2,98.65 238.2,97.7
no net on Bottom Overlay "BOTTOMOVERLAY406" (solid, pour order 0): 240.85,72.1 240.85,73.9 241.35,73.9 241.35,73.4 241,73.4 241,72.6 241.35,72.6 241.35,72.1
no net on Top Paste "TOPPASTE407" (solid, pour order 0): 143.625,36.75 143.625,37.65 144.15,37.65 144.15,36.75
no net on Top Paste "TOPPASTE408" (solid, pour order 0): 143.625,37.85 143.625,38.75 144.15,38.75 144.15,37.85
no net on Top Paste "TOPPASTE409" (solid, pour order 0): 144.35,37.85 144.35,38.75 144.875,38.75 144.875,37.85
no net on Top Paste "TOPPASTE410" (solid, pour order 0): 144.35,36.75 144.35,37.65 144.875,37.65 144.875,36.833 144.792,36.75
no net on Top Paste "TOPPASTE411" (solid, pour order 0): 250.85,95.55 250.85,96.4 251.3,96.4 251.3,95.683 251.167,95.55
no net on Top Paste "TOPPASTE412" (solid, pour order 0): 250.2,95.55 250.2,96.4 250.65,96.4 250.65,95.55
no net on Top Paste "TOPPASTE413" (solid, pour order 0): 250.2,96.6 250.2,97.45 250.65,97.45 250.65,96.6
no net on Top Paste "TOPPASTE414" (solid, pour order 0): 250.85,96.6 250.85,97.45 251.3,97.45 251.3,96.6
no net on Top Paste "TOPPASTE415" (solid, pour order 0): 237.5,96.225 237.5,97.575 238.9,97.575 238.9,96.225
no net on Top Paste "TOPPASTE416" (solid, pour order 0): 239.1,96.225 239.1,97.575 240.5,97.575 240.5,96.225
no net on Top Paste "TOPPASTE417" (solid, pour order 0): 239.1,94.675 239.1,96.025 240.5,96.025 240.5,94.675
no net on Top Paste "TOPPASTE418" (solid, pour order 0): 237.5,94.675 237.5,96.025 238.9,96.025 238.9,94.675
no net on Top Paste "TOPPASTE419" (solid, pour order 0): 140.25,70.5 140.25,73.75 143.15,73.75 143.15,70.5
no net on Top Paste "TOPPASTE420" (solid, pour order 0): 136.85,70.5 136.85,73.75 139.75,73.75 139.75,70.5
no net on Top Paste "TOPPASTE421" (solid, pour order 0): 136.85,74.25 136.85,77.5 139.75,77.5 139.75,74.25
no net on Top Paste "TOPPASTE422" (solid, pour order 0): 140.25,74.25 140.25,77.5 143.15,77.5 143.15,74.25
no net on Top Solder "TOPSOLDER423" (solid, pour order 0): 125.5,87 ccw(c127,87) 128.5,87 ccw(c127,87)
no net on Top Solder "TOPSOLDER424" (solid, pour order 0): 151.5,61 ccw(c153,61) 154.5,61 ccw(c153,61)

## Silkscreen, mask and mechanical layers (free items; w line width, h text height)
Top Overlay:
  drawing of 30719 lines, arcs and shapes, not listed
Bottom Overlay:
  drawing of 33810 lines, arcs and shapes, not listed
Mechanical 3:
  lines w0.001: 19.95,11 ccw(c20,11) 19.965,10.965 20.965,9.965 ccw(c21,10) 21.035,10.035 20.05,11.021 20.05,18.979 21.035,19.965 ccw(c21,20) 20.965,20.035 19.965,19.035 ccw(c20,19) 19.95,19 19.95,11 ; 19.95,21 ccw(c20,21) 20.05,21 20.05,142 ccw(c20,142) 19.95,142 19.95,21 ; 19.95,144 ccw(c20,144) 19.965,143.965 20.965,142.965 ccw(c21,143) 21.035,143.035 20.05,144.021 20.05,151.979 21.035,152.965 ccw(c21,153) 20.965,153.035 19.965,152.035 ccw(c20,152) 19.95,152 19.95,144 ; 19.965,20.965 cw(c20,21) 20.035,21.035 21.035,20.035 cw(c21,20) 20.965,19.965 19.965,20.965 ; 19.965,142.035 ccw(c20,142) 20.035,141.965 21.035,142.965 ccw(c21,143) 20.965,143.035 19.965,142.035 ; 21,9.95 cw(c21,10) 21,10.05 269,10.05 cw(c269,10) 269,9.95 21,9.95 ; 21,19.95 cw(c21,20) 21,20.05 269,20.05 cw(c269,20) 269,19.95 21,19.95 ; 21,142.95 cw(c21,143) 21,143.05 269,143.05 cw(c269,143) 269,142.95 21,142.95 ; 21,152.95 cw(c21,153) 21,153.05 269,153.05 cw(c269,153) 269,152.95 21,152.95 ; 268.965,10.035 ccw(c269,10) 269.035,9.965 270.035,10.965 ccw(c270,11) 270.05,11 270.05,19 ccw(c270,19) 270.035,19.035 269.035,20.035 ccw(c269,20) 268.965,19.965 269.95,18.979 269.95,11.021 268.965,10.035 ; 268.965,20.035 ccw(c269,20) 269.035,19.965 270.035,20.965 ccw(c270,21) 269.965,21.035 268.965,20.035 ; 268.965,142.965 cw(c269,143) 269.035,143.035 270.035,142.035 cw(c270,142) 269.965,141.965 268.965,142.965 ; 268.965,143.035 ccw(c269,143) 269.035,142.965 270.035,143.965 ccw(c270,144) 270.05,144 270.05,152 ccw(c270,152) 270.035,152.035 269.035,153.035 ccw(c269,153) 268.965,152.965 269.95,151.979 269.95,144.021 268.965,143.035 ; 269.95,21 ccw(c270,21) 270.05,21 270.05,142 ccw(c270,142) 269.95,142 269.95,21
